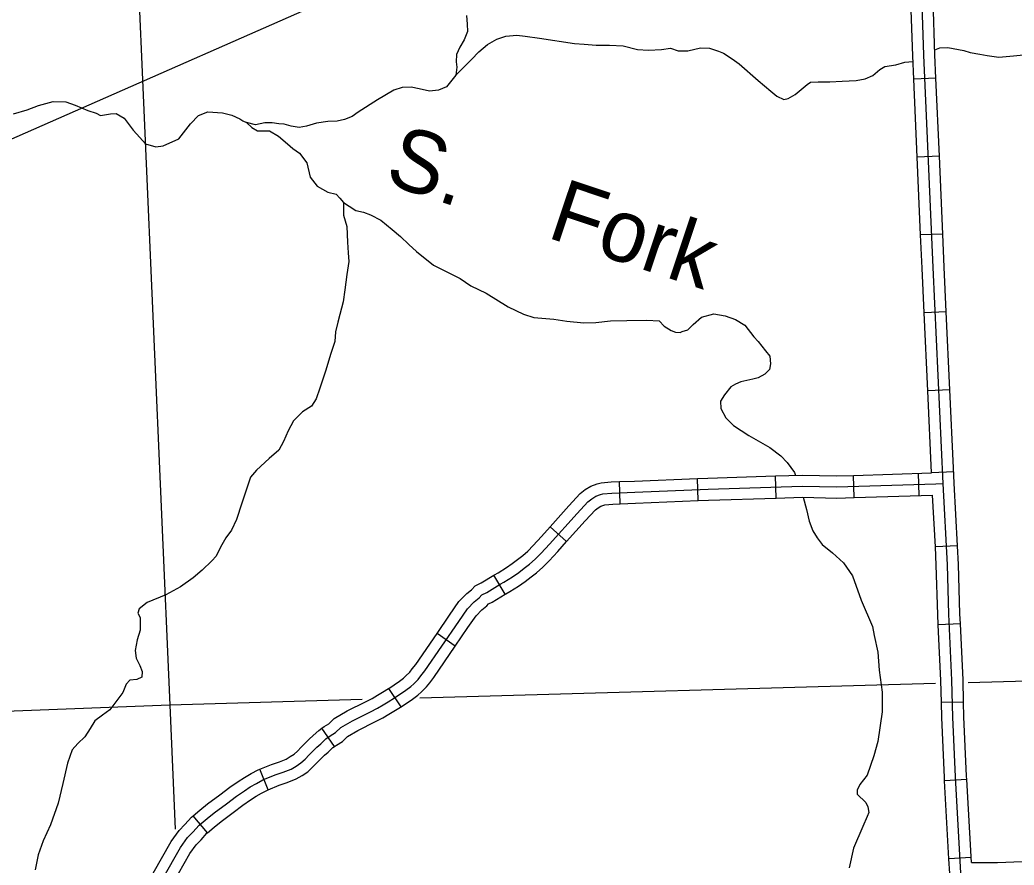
# Model space of a CAD drawing. Extents: x -5566 to 1759129, y -3726 to 731467.
# Drawn here: x -4544.8 to -4493.8, y 394.6 to 438 of the extents above; entities that cross this region are included whole.
import ezdxf

# ---------------------------------------------------------------- set-up
doc = ezdxf.new("R2010")
doc.units = 0
doc.layers.add('Default', color=7, linetype='Continuous')

msp = doc.modelspace()

# ---------------------------------------------------------------- linework, layer by layer
at = {"layer": 'Default'}
for p, q in [((-4497.78, 435.004), (-4498.918, 434.954)), ((-4497.604, 430.998), (-4498.742, 430.948)), ((-4497.429, 426.992), (-4498.567, 426.942)), ((-4497.247, 422.988), (-4498.385, 422.935)), ((-4497.061, 418.983), (-4498.199, 418.93)), ((-4498.646, 413.558), (-4498.682, 414.697)), ((-4496.866, 414.771), (-4498.004, 414.718)), ((-4513.994, 413.132), (-4514.039, 414.27)), ((-4509.987, 413.294), (-4510.033, 414.432)), ((-4505.985, 413.422), (-4506.02, 414.561)), ((-4501.976, 413.455), (-4502.012, 414.593)), ((-4516.748, 411.186), (-4517.596, 411.947)), ((-4496.673, 410.976), (-4497.81, 410.917)), ((-4519.902, 408.484), (-4520.491, 409.459)), ((-4496.521, 406.966), (-4497.659, 406.913)), ((-4522.467, 405.822), (-4523.407, 406.466)), ((-4525.247, 402.701), (-4525.882, 403.648)), ((-4496.359, 402.947), (-4497.498, 402.919)), ((-4528.672, 400.665), (-4529.325, 401.598)), ((-4532.074, 398.441), (-4532.515, 399.491)), ((-4496.198, 398.959), (-4497.335, 398.895)), ((-4535.197, 396.23), (-4535.932, 397.1)), ((-4495.976, 394.955), (-4497.113, 394.892))]:
    msp.add_line(p, q, dxfattribs=at)
for points in [[(-4813.973, 313.686), (-4397.101, 497.071), (-4397.101, 497.071)], [(-4538.835, 441.992), (-4537.134, 402.792)], [(-4496.502, 394.155), (-4496.776, 399.103), (-4496.91, 402.167), (-4496.957, 404.067), (-4497.114, 407.46), (-4497.192, 409.997), (-4497.408, 414.171), (-4497.923, 425.266), (-4498.401, 436.174), (-4498.593, 441.874)], [(-4498.918, 434.954), (-4498.97, 436.152), (-4499.065, 438.967)], [(-4497.78, 435.004), (-4497.832, 436.196), (-4497.926, 439.005)], [(-4521.892, 438.212), (-4521.854, 437.771), (-4521.848, 437.398), (-4522.007, 436.973), (-4522.236, 436.599), (-4522.404, 436.212), (-4522.428, 435.83), (-4522.381, 435.565), (-4522.441, 435.151), (-4522.928, 434.554), (-4523.332, 434.387), (-4523.801, 434.325), (-4524.321, 434.443), (-4524.742, 434.542), (-4525.205, 434.525), (-4525.632, 434.381), (-4526.472, 433.878), (-4527.451, 433.255), (-4527.769, 433.023), (-4528.166, 432.871), (-4528.543, 432.797), (-4529.02, 432.772), (-4529.594, 432.69), (-4530.105, 432.527), (-4530.49, 432.468), (-4530.894, 432.529), (-4531.255, 432.63), (-4531.529, 432.659), (-4531.872, 432.707), (-4532.259, 432.701), (-4532.726, 432.6), (-4533.194, 432.728)], [(-4522.441, 435.151), (-4521.643, 435.957), (-4521.263, 436.344), (-4520.806, 436.727), (-4520.33, 437.003), (-4519.88, 437.164), (-4519.313, 437.215), (-4518.878, 437.155), (-4518.138, 437.052), (-4516.351, 436.773), (-4515.849, 436.738), (-4515.24, 436.691), (-4514.549, 436.701), (-4513.85, 436.658), (-4513.114, 436.479), (-4512.551, 436.43), (-4511.877, 436.477), (-4511.408, 436.54), (-4511.016, 436.402), (-4510.523, 436.404), (-4509.875, 436.55), (-4509.419, 436.536), (-4508.951, 436.392), (-4508.697, 436.287), (-4508.238, 435.999), (-4507.879, 435.73), (-4506.907, 434.881), (-4506.257, 434.325), (-4505.959, 434.069), (-4505.589, 433.907), (-4505.362, 433.954), (-4505.013, 434.164), (-4504.387, 434.682), (-4504.224, 434.802), (-4503.822, 434.817), (-4503.238, 434.808), (-4502.594, 434.846), (-4501.874, 434.887), (-4501.414, 434.965), (-4501.018, 435.139), (-4500.657, 435.449), (-4500.404, 435.603), (-4499.846, 435.685), (-4499.369, 435.818), (-4498.958, 435.86)], [(-4497.841, 436.455), (-4497.581, 436.557), (-4497.172, 436.57), (-4496.352, 436.42), (-4496.027, 436.31), (-4495.523, 436.229), (-4495.156, 436.166), (-4494.554, 436.081), (-4493.804, 436.139), (-4492.919, 436.232)], [(-4498.742, 430.948), (-4498.918, 434.954)], [(-4497.604, 430.998), (-4497.78, 435.004)], [(-4545.159, 433.158), (-4544.453, 433.366), (-4543.877, 433.6), (-4543.125, 433.795), (-4542.479, 433.78), (-4541.987, 433.615), (-4541.339, 433.341), (-4540.917, 433.201), (-4540.693, 433.079), (-4540.181, 433.168), (-4539.895, 433.191), (-4539.478, 432.941), (-4539.018, 432.335), (-4538.677, 431.959), (-4538.377, 431.619), (-4537.848, 431.478), (-4537.465, 431.527), (-4536.674, 431.887), (-4536.061, 432.652), (-4535.666, 433.073), (-4535.187, 433.275), (-4534.427, 433.225), (-4533.951, 433.097), (-4533.535, 432.914), (-4533.379, 432.805), (-4533.194, 432.728), (-4532.926, 432.463), (-4532.632, 432.299), (-4532.009, 432.293), (-4531.546, 432.026), (-4531.083, 431.618), (-4530.811, 431.377), (-4530.478, 431.146), (-4530.101, 430.652), (-4529.921, 429.913), (-4529.567, 429.442), (-4529.018, 429.144), (-4528.594, 429.034), (-4528.398, 428.837), (-4528.216, 428.609), (-4527.921, 428.422), (-4527.573, 428.201), (-4527.189, 428.107), (-4526.82, 427.974), (-4526.294, 427.707)], [(-4498.567, 426.942), (-4498.742, 430.948)], [(-4497.429, 426.992), (-4497.604, 430.998)], [(-4528.216, 428.609), (-4528.208, 427.962), (-4528.037, 427.372), (-4527.997, 426.57), (-4527.97, 426.03), (-4527.942, 425.572), (-4528.043, 424.911), (-4528.144, 424.13), (-4528.228, 423.499), (-4528.395, 422.856), (-4528.502, 422.462), (-4528.621, 421.961), (-4528.662, 421.467), (-4528.867, 420.85), (-4529.13, 419.941), (-4529.433, 419.076), (-4529.61, 418.521), (-4529.855, 418.154), (-4530.315, 417.863), (-4530.776, 417.397), (-4531.054, 416.884), (-4531.299, 416.334), (-4531.526, 415.884), (-4532.026, 415.454), (-4532.673, 414.867), (-4532.986, 414.505), (-4533.171, 413.942), (-4533.439, 413.162), (-4533.712, 412.322), (-4533.958, 411.779), (-4534.262, 411.38), (-4534.533, 410.897), (-4534.752, 410.447), (-4534.978, 410.195), (-4535.462, 409.728), (-4535.926, 409.323), (-4536.584, 408.857), (-4537.344, 408.456), (-4538.294, 408.064), (-4538.707, 407.729), (-4538.775, 407.505), (-4538.661, 407.296), (-4538.652, 406.641), (-4538.801, 406.14), (-4538.918, 405.595), (-4538.857, 405.193), (-4538.669, 404.819), (-4538.552, 404.51), (-4538.564, 404.22), (-4538.818, 404.112), (-4539.181, 404.076), (-4539.371, 403.856), (-4539.538, 403.438), (-4540.211, 402.537), (-4540.596, 402.272), (-4540.988, 401.976), (-4541.224, 401.586), (-4541.489, 401.158), (-4541.849, 400.817), (-4542.141, 400.494), (-4542.381, 399.807), (-4542.632, 398.754), (-4542.861, 397.747), (-4543.26, 396.635), (-4543.633, 395.814), (-4543.896, 395.103), (-4544.042, 394.328)], [(-4526.294, 427.707), (-4525.705, 427.22), (-4525.291, 426.86), (-4524.858, 426.449), (-4524.465, 426.085), (-4523.582, 425.393), (-4522.802, 425.006), (-4522.213, 424.699), (-4521.672, 424.338), (-4520.879, 423.953), (-4519.754, 423.252), (-4518.964, 422.87), (-4518.427, 422.699), (-4517.415, 422.62), (-4516.733, 422.508), (-4515.867, 422.424), (-4515.253, 422.439), (-4514.497, 422.534), (-4513.655, 422.55), (-4512.635, 422.571), (-4511.999, 422.532), (-4511.74, 422.257), (-4511.379, 422.037), (-4511.151, 421.943), (-4510.924, 421.935), (-4510.814, 421.982), (-4510.531, 422.076), (-4510.254, 422.337), (-4509.817, 422.724), (-4509.193, 422.899), (-4508.6, 422.793), (-4508.082, 422.602), (-4507.595, 422.312), (-4507.14, 421.707), (-4506.912, 421.463), (-4506.527, 420.992), (-4506.315, 420.717), (-4506.276, 420.325), (-4506.331, 420.034), (-4506.566, 419.798), (-4506.905, 419.607), (-4507.191, 419.529), (-4507.807, 419.39), (-4508.074, 419.272), (-4508.317, 419.139), (-4508.634, 418.726), (-4508.851, 418.408), (-4508.828, 418.023), (-4508.576, 417.552), (-4508.176, 417.16), (-4507.383, 416.641), (-4506.315, 416.029), (-4505.75, 415.602), (-4505.418, 415.248), (-4505.043, 414.743), (-4504.987, 414.593)], [(-4498.385, 422.935), (-4498.492, 425.241), (-4498.567, 426.942)], [(-4497.247, 422.988), (-4497.354, 425.292), (-4497.429, 426.992)], [(-4498.199, 418.93), (-4498.385, 422.935)], [(-4497.061, 418.983), (-4497.247, 422.988)], [(-4498.004, 414.718), (-4498.199, 418.93)], [(-4496.876, 414.977), (-4497.061, 418.983)], [(-4502.012, 414.593), (-4498.004, 414.718)], [(-4496.673, 410.976), (-4496.839, 414.199), (-4496.876, 414.977)], [(-4537.49, 393.886), (-4536.59, 395.466), (-4536.217, 395.983), (-4535.942, 396.259), (-4535.621, 396.617), (-4535.22, 396.955), (-4534.849, 397.26), (-4534.213, 397.724), (-4533.711, 398.115), (-4533.303, 398.389), (-4533, 398.591), (-4532.687, 398.769), (-4532.352, 398.942), (-4531.716, 399.208), (-4531.304, 399.345), (-4530.892, 399.505), (-4530.647, 399.659), (-4530.395, 399.82), (-4530.174, 400.019), (-4529.969, 400.232), (-4529.809, 400.398), (-4529.582, 400.627), (-4529.383, 400.802), (-4529.119, 401.048), (-4528.889, 401.208), (-4528.614, 401.378), (-4528.343, 401.641), (-4527.747, 401.985), (-4526.821, 402.448), (-4526.462, 402.635), (-4526.18, 402.805), (-4525.919, 402.959), (-4525.591, 403.157), (-4525.005, 403.55), (-4524.759, 403.737), (-4524.606, 403.878), (-4524.378, 404.107), (-4524.231, 404.291), (-4524.032, 404.546), (-4522.288, 407.091), (-4521.841, 407.743), (-4521.495, 408.098), (-4521.24, 408.301), (-4521.105, 408.448), (-4520.856, 408.574), (-4520.158, 408.995), (-4519.974, 409.105), (-4519.535, 409.386), (-4519.207, 409.597), (-4518.922, 409.829), (-4518.648, 410.037), (-4518.357, 410.283), (-4518.058, 410.599), (-4517.625, 411.062), (-4516.213, 412.636), (-4515.662, 413.234), (-4515.463, 413.392), (-4515.252, 413.521), (-4515.006, 413.615), (-4514.883, 413.644), (-4514.42, 413.685), (-4513.242, 413.732), (-4509.479, 413.884), (-4504.643, 414.034), (-4502.876, 413.996), (-4497.777, 414.155), (-4497.408, 414.171)], [(-4517.596, 411.947), (-4516.634, 413.019), (-4516.051, 413.652), (-4515.79, 413.86), (-4515.504, 414.034), (-4515.174, 414.16), (-4514.974, 414.208), (-4514.456, 414.254), (-4514.039, 414.27)], [(-4514.039, 414.27), (-4513.265, 414.301), (-4510.033, 414.432)], [(-4510.033, 414.432), (-4509.5, 414.454), (-4506.02, 414.561)], [(-4506.02, 414.561), (-4504.646, 414.603), (-4502.878, 414.566), (-4502.012, 414.593)], [(-4513.994, 413.132), (-4513.219, 413.163), (-4509.987, 413.294)], [(-4509.987, 413.294), (-4509.459, 413.315), (-4505.985, 413.422)], [(-4505.985, 413.422), (-4504.64, 413.464), (-4502.873, 413.427), (-4501.976, 413.455)], [(-4504.594, 413.465), (-4504.435, 412.837), (-4504.288, 412.236), (-4504.096, 411.741), (-4503.889, 411.387), (-4503.622, 411.041), (-4503.096, 410.611), (-4502.52, 410.1), (-4502.068, 409.431), (-4501.619, 408.178), (-4501.035, 406.832), (-4500.95, 406.37), (-4500.768, 405.513), (-4500.692, 404.585), (-4500.535, 403.447), (-4500.535, 402.446), (-4500.767, 400.923), (-4500.968, 400.189), (-4501.319, 399.193), (-4501.69, 398.704), (-4501.822, 398.412), (-4501.82, 398.214), (-4501.388, 397.789), (-4501.282, 397.568), (-4501.233, 397.274), (-4501.306, 397.062), (-4501.527, 396.547), (-4502.008, 395.446), (-4502.237, 394.433)], [(-4501.976, 413.455), (-4497.948, 413.58)], [(-4497.81, 410.917), (-4497.948, 413.58)], [(-4516.748, 411.186), (-4515.791, 412.253), (-4515.273, 412.815), (-4515.136, 412.924), (-4515, 413.008), (-4514.838, 413.069), (-4514.791, 413.08), (-4514.383, 413.117), (-4513.994, 413.132)], [(-4520.491, 409.459), (-4520.451, 409.483), (-4520.274, 409.589), (-4519.842, 409.865), (-4519.541, 410.059), (-4519.274, 410.277), (-4519.005, 410.481), (-4518.749, 410.697), (-4518.473, 410.989), (-4518.045, 411.447), (-4517.596, 411.947)], [(-4519.902, 408.484), (-4519.864, 408.507), (-4519.675, 408.62), (-4519.227, 408.907), (-4518.872, 409.135), (-4518.569, 409.381), (-4518.292, 409.592), (-4517.965, 409.868), (-4517.643, 410.209), (-4517.205, 410.677), (-4516.748, 411.186)], [(-4497.659, 406.913), (-4497.683, 407.438), (-4497.762, 409.973), (-4497.81, 410.917)], [(-4496.521, 406.966), (-4496.545, 407.481), (-4496.623, 410.02), (-4496.673, 410.976)], [(-4523.407, 406.466), (-4522.758, 407.413), (-4522.283, 408.106), (-4521.878, 408.522), (-4521.63, 408.719), (-4521.455, 408.909), (-4521.132, 409.072), (-4520.491, 409.459)], [(-4522.467, 405.822), (-4521.818, 406.769), (-4521.399, 407.381), (-4521.113, 407.675), (-4520.851, 407.883), (-4520.756, 407.986), (-4520.58, 408.075), (-4519.902, 408.484)], [(-4497.498, 402.919), (-4497.526, 404.046), (-4497.659, 406.913)], [(-4496.359, 402.947), (-4496.388, 404.087), (-4496.521, 406.966)], [(-4525.882, 403.648), (-4525.336, 404.013), (-4525.125, 404.174), (-4525.002, 404.288), (-4524.804, 404.487), (-4524.678, 404.644), (-4524.492, 404.883), (-4523.407, 406.466)], [(-4525.247, 402.701), (-4524.673, 403.086), (-4524.392, 403.3), (-4524.211, 403.467), (-4523.952, 403.727), (-4523.784, 403.938), (-4523.572, 404.209), (-4522.467, 405.822)], [(-4477.92, 404.451), (-4496.121, 403.941)], [(-4529.325, 401.598), (-4529.203, 401.684), (-4528.966, 401.83), (-4528.688, 402.099), (-4528.017, 402.486), (-4527.08, 402.955), (-4526.741, 403.131), (-4526.472, 403.294), (-4526.211, 403.449), (-4525.896, 403.638), (-4525.882, 403.648)], [(-4497.805, 403.894), (-4524.298, 403.152)], [(-4527.245, 403.069), (-4537.134, 402.792)], [(-4496.198, 398.959), (-4496.207, 399.131), (-4496.341, 402.186), (-4496.359, 402.947)], [(-4537.134, 402.792), (-4553.583, 402.146)], [(-4537.134, 402.792), (-4536.854, 396.42)], [(-4528.672, 400.665), (-4528.576, 400.732), (-4528.263, 400.926), (-4527.997, 401.182), (-4527.477, 401.483), (-4526.562, 401.94), (-4526.183, 402.138), (-4525.888, 402.316), (-4525.627, 402.47), (-4525.285, 402.676), (-4525.247, 402.701)], [(-4497.335, 398.895), (-4497.345, 399.075), (-4497.479, 402.147), (-4497.498, 402.919)], [(-4532.515, 399.491), (-4531.916, 399.742), (-4531.496, 399.881), (-4531.149, 400.016), (-4530.952, 400.14), (-4530.741, 400.275), (-4530.571, 400.428), (-4530.379, 400.627), (-4530.215, 400.796), (-4529.972, 401.042), (-4529.765, 401.224), (-4529.478, 401.491), (-4529.325, 401.598)], [(-4532.074, 398.441), (-4531.516, 398.675), (-4531.111, 398.809), (-4530.635, 398.994), (-4530.342, 399.178), (-4530.048, 399.366), (-4529.778, 399.609), (-4529.56, 399.836), (-4529.402, 399.999), (-4529.191, 400.212), (-4529.001, 400.379), (-4528.76, 400.604), (-4528.672, 400.665)], [(-4535.932, 397.1), (-4535.585, 397.393), (-4535.198, 397.711), (-4534.556, 398.178), (-4534.045, 398.577), (-4533.62, 398.863), (-4533.299, 399.076), (-4532.959, 399.27), (-4532.592, 399.458), (-4532.515, 399.491)], [(-4497.113, 394.892), (-4497.335, 398.895)], [(-4495.961, 394.701), (-4496.198, 398.959)], [(-4535.197, 396.23), (-4534.856, 396.518), (-4534.501, 396.809), (-4533.87, 397.269), (-4533.377, 397.654), (-4532.987, 397.915), (-4532.7, 398.106), (-4532.415, 398.269), (-4532.111, 398.425), (-4532.074, 398.441)], [(-4538.268, 393.585), (-4537.994, 394.151), (-4537.07, 395.774), (-4536.652, 396.354), (-4536.356, 396.65), (-4536.019, 397.027), (-4535.932, 397.1)], [(-4537.242, 393.089), (-4536.985, 393.621), (-4536.111, 395.157), (-4535.782, 395.613), (-4535.528, 395.867), (-4535.223, 396.208), (-4535.197, 396.23)], [(-4496.95, 390.878), (-4496.973, 391.222), (-4497.071, 394.13), (-4497.113, 394.892)], [(-4495.961, 394.701), (-4494.621, 394.701), (-4492.516, 394.783)]]:
    msp.add_lwpolyline(points, dxfattribs=at)

# ---------------------------------------------------------------- texts
msp.add_text('S.    Fork', height=3.2048, rotation=341.4896, dxfattribs=at).set_placement((-4526.19, 429.639))

doc.saveas('drawing.dxf')
